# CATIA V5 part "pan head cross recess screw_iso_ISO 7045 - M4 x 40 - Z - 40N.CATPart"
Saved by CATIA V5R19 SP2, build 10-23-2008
Part number: pan head cross recess screw_iso_ISO 7045 - M4 x 40 - Z - 40N
Revision: ANY
Definition: UNKNOWN
Nomenclature: pan head cross recess screw_iso_ISO 7045 - M4 x 40 - Z - 40N
Source: Unknown
Bounding box of the stored display mesh (mm): x 0.079 to 43.1, y -4 to 4, z -4 to 4
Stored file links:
  Z:\fausse table rondelle-20220905T211342Z-001\fausse table rondelle\pan head cross recess screw_iso_ISO 7045 - M4 x 40 - Z - 40N.CATPart
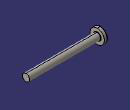
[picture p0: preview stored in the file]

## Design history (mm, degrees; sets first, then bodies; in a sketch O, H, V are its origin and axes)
AxisSystem1: origin (0, 0, 0), X (1, 0, 0), Y (0, 1, 0), Z (0, 0, 1)
Body1 "RecessCore" (main body)
  Solid1: solid without history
